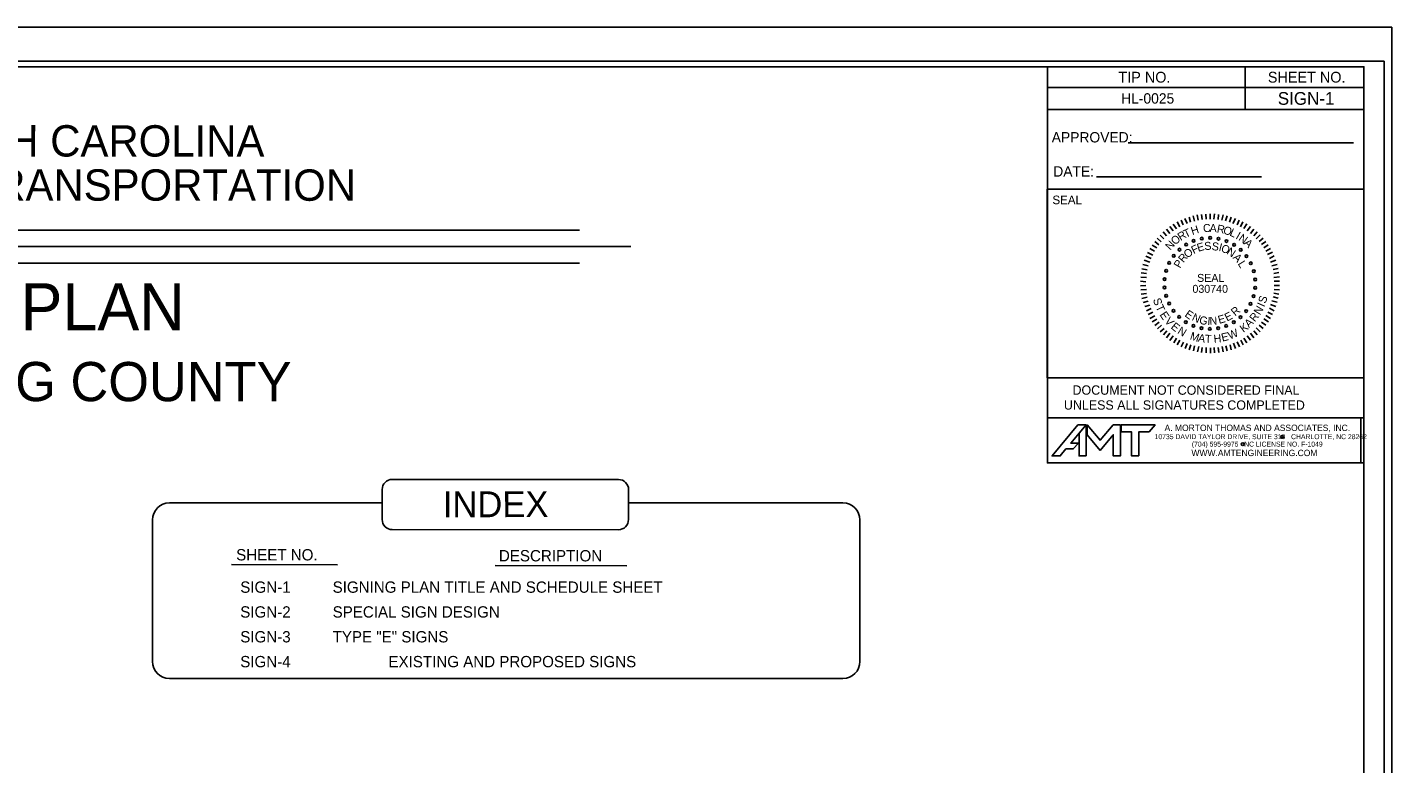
# Model space of a CAD drawing. Extents: x 2088591 to 2091186, y 751169 to 752405.
# Drawn here: x 2089946 to 2090752, y 751970 to 752405 of the extents above; entities that cross this region are included whole.
import ezdxf

# ---------------------------------------------------------------- set-up
doc = ezdxf.new("R2010")
doc.units = 0
for name, color, linetype in [('Default', 7, 'Continuous'), ('DEV PRELIMINARY STAMP CELL', 7, 'Continuous'), ('MARK LEFT TURN ARROW CELL', 7, 'Continuous'), ('Sheet Block Title CELL', 7, 'Continuous'), ('Sheet Data Field CELL', 7, 'Continuous'), ('Sheet Plan CELL', 7, 'Continuous'), ('Sheet Plot Border Inside CELL', 7, 'Continuous'), ('Sheet Plot Border Outside CELL', 7, 'Continuous'), ('Sheet Sticker Incomplete CELL', 7, 'Continuous'), ('Sheet Title CELL', 7, 'Continuous'), ('Typical Detail Wedge1 CELL', 7, 'Continuous')]:
    doc.layers.add(name, color=color, linetype=linetype)

msp = doc.modelspace()

# ---------------------------------------------------------------- linework, layer by layer
at = {"layer": 'Default'}
msp.add_line((2090595.95, 752336.5), (2090728.98, 752336.5), dxfattribs=at)
at = {"layer": 'DEV PRELIMINARY STAMP CELL'}
for p, q in [((2090627.21, 752291.02), (2090628.34, 752288.14)), ((2090629.34, 752292.02), (2090630.84, 752289.02)), ((2090631.96, 752292.77), (2090632.84, 752289.77)), ((2090634.34, 752293.52), (2090635.21, 752290.39)), ((2090636.71, 752294.02), (2090637.34, 752291.02)), ((2090639.34, 752294.39), (2090639.59, 752291.39)), ((2090641.71, 752294.52), (2090642.09, 752291.52)), ((2090644.34, 752294.77), (2090644.34, 752291.52)), ((2090646.96, 752294.77), (2090646.59, 752291.52)), ((2090649.34, 752294.39), (2090649.09, 752291.39)), ((2090651.96, 752294.02), (2090651.34, 752291.02)), ((2090654.34, 752293.52), (2090653.46, 752290.52)), ((2090656.71, 752292.77), (2090655.84, 752289.77)), ((2090659.34, 752292.02), (2090657.84, 752289.02)), ((2090661.46, 752291.02), (2090660.34, 752288.14)), ((2090616.59, 752284.02), (2090618.59, 752281.64)), ((2090618.59, 752285.64), (2090620.59, 752283.02)), ((2090620.59, 752287.14), (2090622.46, 752284.64)), ((2090622.59, 752288.52), (2090624.46, 752285.77)), ((2090624.96, 752290.02), (2090626.46, 752287.02)), ((2090663.71, 752290.02), (2090662.21, 752287.02)), ((2090666.09, 752288.77), (2090664.21, 752286.02)), ((2090668.09, 752287.14), (2090666.21, 752284.64)), ((2090670.09, 752285.64), (2090668.09, 752283.14)), ((2090672.09, 752284.02), (2090670.09, 752281.77)), ((2090610.09, 752276.27), (2090612.84, 752274.64)), ((2090611.71, 752278.39), (2090614.09, 752276.39)), ((2090613.09, 752280.39), (2090615.46, 752278.27)), ((2090614.84, 752282.14), (2090617.09, 752280.02)), ((2090673.84, 752282.39), (2090671.59, 752280.02)), ((2090675.59, 752280.39), (2090673.21, 752278.39)), ((2090677.21, 752278.39), (2090674.59, 752276.64)), ((2090678.59, 752276.39), (2090675.96, 752274.64)), ((2090605.46, 752267.27), (2090608.71, 752266.27)), ((2090606.46, 752269.64), (2090609.46, 752268.39)), ((2090607.46, 752271.89), (2090610.46, 752270.39)), ((2090608.71, 752274.27), (2090611.46, 752272.64)), ((2090679.96, 752274.27), (2090677.21, 752272.64)), ((2090681.21, 752272.02), (2090678.21, 752270.64)), ((2090682.21, 752269.89), (2090679.46, 752268.39)), ((2090683.21, 752267.27), (2090679.96, 752266.27)), ((2090603.71, 752259.89), (2090606.84, 752259.52)), ((2090604.09, 752262.27), (2090607.21, 752261.64)), ((2090604.71, 752264.89), (2090607.84, 752264.02)), ((2090683.96, 752264.89), (2090680.84, 752264.02)), ((2090684.59, 752262.52), (2090681.46, 752261.89)), ((2090684.96, 752260.14), (2090681.96, 752259.52)), ((2090603.34, 752254.89), (2090606.46, 752254.64)), ((2090603.34, 752252.27), (2090606.46, 752252.52)), ((2090603.46, 752257.27), (2090606.71, 752257.14)), ((2090685.21, 752257.52), (2090681.96, 752257.14)), ((2090685.34, 752254.89), (2090682.21, 752254.89)), ((2090685.34, 752252.52), (2090682.21, 752252.52)), ((2090603.46, 752249.77), (2090606.71, 752250.14)), ((2090603.71, 752247.27), (2090606.84, 752247.77)), ((2090604.09, 752244.77), (2090607.21, 752245.52)), ((2090604.84, 752242.39), (2090607.84, 752243.14)), ((2090683.96, 752242.52), (2090680.84, 752243.39)), ((2090684.59, 752244.89), (2090681.46, 752245.77)), ((2090684.96, 752247.27), (2090681.96, 752247.89)), ((2090685.21, 752249.89), (2090682.21, 752250.14)), ((2090605.71, 752240.02), (2090608.71, 752240.89)), ((2090606.71, 752237.52), (2090609.46, 752238.77)), ((2090607.71, 752235.39), (2090610.46, 752236.77)), ((2090608.84, 752233.02), (2090611.71, 752234.52)), ((2090679.96, 752233.02), (2090677.21, 752234.77)), ((2090681.21, 752235.39), (2090678.46, 752236.77)), ((2090682.21, 752237.52), (2090679.46, 752239.02)), ((2090683.21, 752240.02), (2090679.96, 752241.14)), ((2090610.09, 752231.02), (2090612.84, 752232.64)), ((2090611.71, 752228.77), (2090614.21, 752230.77)), ((2090613.21, 752226.77), (2090615.59, 752229.02)), ((2090614.84, 752225.02), (2090617.21, 752227.14)), ((2090673.84, 752225.02), (2090671.59, 752227.39)), ((2090675.59, 752227.02), (2090673.21, 752229.02)), ((2090677.21, 752229.02), (2090674.59, 752230.77)), ((2090678.84, 752231.02), (2090675.96, 752232.77)), ((2090616.84, 752223.27), (2090618.84, 752225.64)), ((2090618.59, 752221.64), (2090620.59, 752224.27)), ((2090620.59, 752220.02), (2090622.46, 752222.64)), ((2090622.84, 752218.64), (2090624.46, 752221.39)), ((2090624.96, 752217.39), (2090626.46, 752220.27)), ((2090627.21, 752216.27), (2090628.59, 752219.02)), ((2090659.34, 752215.27), (2090658.09, 752218.39)), ((2090661.71, 752216.27), (2090660.34, 752219.27)), ((2090663.84, 752217.39), (2090662.46, 752220.27)), ((2090666.09, 752218.64), (2090664.21, 752221.39)), ((2090668.09, 752220.27), (2090666.21, 752222.77)), ((2090670.21, 752221.64), (2090668.09, 752224.27)), ((2090672.09, 752223.39), (2090670.09, 752225.64)), ((2090629.59, 752215.27), (2090630.84, 752218.27)), ((2090631.96, 752214.39), (2090632.96, 752217.39)), ((2090634.59, 752213.89), (2090635.21, 752216.89)), ((2090636.96, 752213.27), (2090637.59, 752216.39)), ((2090639.34, 752212.89), (2090639.71, 752215.89)), ((2090641.96, 752212.64), (2090642.09, 752215.89)), ((2090644.59, 752212.52), (2090644.59, 752215.64)), ((2090646.96, 752212.64), (2090646.71, 752215.89)), ((2090649.46, 752212.89), (2090649.09, 752215.89)), ((2090652.09, 752213.27), (2090651.46, 752216.39)), ((2090654.46, 752213.89), (2090653.71, 752216.89)), ((2090656.84, 752214.39), (2090656.09, 752217.39))]:
    msp.add_line(p, q, dxfattribs=at)
for centre in [(2090630.17, 752276.53), (2090634.62, 752278.73), (2090639.39, 752280.06), (2090644.33, 752280.5), (2090649.27, 752280.03), (2090654.03, 752278.65), (2090658.46, 752276.42), (2090622.85, 752269.91), (2090626.21, 752273.56), (2090662.4, 752273.42), (2090665.73, 752269.74), (2090618.42, 752261.09), (2090620.23, 752265.71), (2090668.32, 752265.52), (2090670.09, 752260.89), (2090617.47, 752251.27), (2090617.49, 752256.22), (2090670.96, 752251.06), (2090670.98, 752256.01), (2090618.36, 752246.39), (2090620.14, 752241.76), (2090670.03, 752246.19), (2090622.73, 752237.54), (2090626.05, 752233.86), (2090662.25, 752233.72), (2090665.6, 752237.37), (2090668.22, 752241.57), (2090630, 752230.86), (2090634.43, 752228.63), (2090639.19, 752227.26), (2090644.12, 752226.78), (2090649.06, 752227.22), (2090653.83, 752228.56), (2090658.28, 752230.75)]:
    msp.add_circle(centre, 0.788, dxfattribs=at)
at = {"layer": 'MARK LEFT TURN ARROW CELL'}
for p, q in [((2090665.02, 752356.38), (2090665.04, 752381.34)), ((2090577.26, 752316.61), (2090674.7, 752316.61))]:
    msp.add_line(p, q, dxfattribs=at)
at = {"layer": 'Sheet Block Title CELL'}
msp.add_lwpolyline([(2090751.52, 752404.71), (2089068.61, 752404.71), (2089068.61, 751308.81), (2090751.52, 751308.81)], close=True, dxfattribs=at)
at = {"layer": 'Sheet Plan CELL'}
for p, q in [((2090751.52, 752404.71), (2090751.52, 752404.71)), ((2090747.03, 752384.71), (2090747.03, 752384.71))]:
    msp.add_line(p, q, dxfattribs=at)
at = {"layer": 'Sheet Plot Border Outside CELL'}
msp.add_lwpolyline([(2090548.29, 752174.37), (2090733.32, 752174.37), (2090733.32, 752147.74), (2090548.29, 752147.74)], close=True, dxfattribs=at)
at = {"layer": 'Sheet Sticker Incomplete CELL'}
for points in [[(2090735.1, 752381.4), (2089235.1, 752381.4), (2089235.1, 751331.4), (2090735.1, 751331.4)], [(2090548.29, 752381.4), (2090735.1, 752381.4), (2090735.1, 752147.74), (2090548.29, 752147.74)], [(2090548.29, 752381.4), (2090735.1, 752381.4), (2090735.1, 752356.33), (2090548.29, 752356.33)], [(2090548.29, 752381.4), (2090665.04, 752381.4), (2090665.04, 752369.19), (2090548.29, 752369.19)], [(2090665.04, 752381.4), (2090735.1, 752381.4), (2090735.1, 752369.19), (2090665.04, 752369.19)], [(2090548.29, 752369.19), (2090665.02, 752369.19), (2090665.02, 752356.33), (2090548.29, 752356.33)], [(2090665.04, 752369.19), (2090735.1, 752369.19), (2090735.1, 752356.33), (2090665.04, 752356.33)], [(2090548.25, 752309.27), (2090735.1, 752309.27), (2090735.1, 752197.87), (2090548.25, 752197.87)], [(2090548.29, 752197.87), (2090735.1, 752197.87), (2090735.1, 752174.37), (2090548.29, 752174.37)], [(2090548.29, 752174.37), (2090733.32, 752174.37), (2090733.32, 752147.74), (2090548.29, 752147.74)]]:
    msp.add_lwpolyline(points, close=True, dxfattribs=at)
for points in [[(2090566.97, 752165.32), (2090571.17, 752170.24), (2090566.27, 752170.24), (2090551.08, 752151.94), (2090555.83, 752151.94), (2090559.24, 752156.06), (2090563.58, 752156.06), (2090566.57, 752159.51), (2090562.07, 752159.51), (2090566.97, 752165.32)], [(2090571.17, 752151.94), (2090571.17, 752170.24), (2090566.97, 752165.32), (2090566.97, 752151.94), (2090571.17, 752151.94)], [(2090579.4, 752155.17), (2090587.17, 752164.43), (2090587.17, 752151.94), (2090591.36, 752151.94), (2090591.36, 752170.24), (2090587.17, 752170.24), (2090579.4, 752161.11), (2090571.71, 752170.24), (2090571.71, 752164.41), (2090579.4, 752155.17)], [(2090602.22, 752151.94), (2090602.22, 752166.04), (2090608.3, 752166.04), (2090611.81, 752170.24), (2090591.9, 752170.24), (2090591.9, 752166.04), (2090598.03, 752166.04), (2090598.03, 752151.94), (2090602.22, 752151.94)]]:
    msp.add_lwpolyline(points, dxfattribs=at)
for centre in [(2090686.81, 752163.18), (2090663.55, 752158.82)]:
    msp.add_circle(centre, 0.833, dxfattribs=at)
at = {"layer": 'Sheet Title CELL'}
for p, q in [((2089579.98, 752285.08), (2090272.09, 752285.08)), ((2089548.01, 752275.34), (2090302.43, 752275.34)), ((2089579.98, 752265.58), (2090272.09, 752265.58)), ((2090155.64, 752114.41), (2090155.65, 752132.04)), ((2090301.06, 752114.34), (2090301.07, 752131.98)), ((2090066.74, 752087.77), (2090129.3, 752087.74)), ((2090222.31, 752087.2), (2090300.04, 752087.17))]:
    msp.add_line(p, q, dxfattribs=at)
for points in [[(2090161.66, 752138.04), (2090295.07, 752137.98)], [(2090030.06, 752124.15), (2090155.65, 752124.15)], [(2090301.07, 752124.15), (2090427.62, 752124.15)], [(2090020.06, 752030.62), (2090020.06, 752114.15)], [(2090437.62, 752114.15), (2090437.62, 752030.62)], [(2090161.64, 752108.41), (2090295.06, 752108.35)], [(2090427.62, 752020.62), (2090030.06, 752020.62)]]:
    msp.add_lwpolyline(points, dxfattribs=at)
for centre, radius, start, end in [((2090161.65, 752132.04), 6, 89.97341, 179.97341), ((2090295.07, 752131.98), 6, 359.97341, 89.97341), ((2090030.06, 752114.15), 10, 90, 180), ((2090427.62, 752114.15), 10, 0, 90), ((2090161.64, 752114.41), 6, 179.97341, 269.97341), ((2090295.06, 752114.35), 6, 269.97341, 359.97341), ((2090030.06, 752030.62), 10, 180, 270), ((2090427.62, 752030.62), 10, 270, 0)]:
    msp.add_arc(centre, radius, start, end, dxfattribs=at)
at = {"layer": 'Typical Detail Wedge1 CELL'}
msp.add_lwpolyline([(2090747.03, 752384.71), (2089081.6, 752384.71), (2089081.6, 751328.81), (2090747.03, 751328.81)], close=True, dxfattribs=at)

# ---------------------------------------------------------------- texts
at = {"layer": 'Default'}
for s, height, p in [('TIP NO.', 6.358, (2090590.22, 752372.11)), ('SHEET NO.', 6.358, (2090678.42, 752372.11)), ('HL-0025', 6.11, (2090591.81, 752359.71)), ('APPROVED:', 6.11, (2090550.85, 752336.79)), ('DATE:', 6.11, (2090551.76, 752316.65)), ('SIGN-1          SIGNING PLAN TITLE AND SCHEDULE SHEET', 6.6709, (2090071.88, 752071.19)), ('SIGN-2          SPECIAL SIGN DESIGN', 6.6709, (2090071.88, 752056.55)), ('SIGN-3          TYPE "E" SIGNS', 6.6709, (2090071.88, 752041.9)), ('SIGN-4   ', 6.671, (2090071.88, 752027.25)), ('   EXISTING AND PROPOSED SIGNS', 6.6709, (2090151.93, 752027.25))]:
    msp.add_text(s, height=height, dxfattribs=at).set_placement(p)
for s, height, rotation, p in [('SEAL', 5.094, 359.96412, (2090551.27, 752300.36)), ('INDEX', 15.257, 0.15565, (2090191.46, 752115.68)), ('SHEET NO.', 6.671, 359.97341, (2090069.46, 752090.28)), ('DESCRIPTION', 6.6709, 359.97341, (2090224.55, 752089.71))]:
    msp.add_text(s, height=height, rotation=rotation, dxfattribs=at).set_placement(p)
at = {"layer": 'DEV PRELIMINARY STAMP CELL'}
for s, height, rotation, p in [('R', 4.72, 32.17545, (2090626.96, 752278.64)), ('T', 4.72, 25.43578, (2090629.96, 752280.39)), ('H', 4.72, 17.74335, (2090633.84, 752282.14)), ('C', 4.72, 4.93991, (2090640.34, 752283.77)), ('A', 4.72, 357.97486, (2090643.96, 752284.02)), ('R', 4.72, 350.02156, (2090648.09, 752283.77)), ('O', 4.72, 343.0868, (2090651.71, 752283.14)), ('L', 4.72, 335.7459, (2090655.46, 752282.02)), ('I', 4.72, 330.80596, (2090659.09, 752280.27)), ('N', 4.72, 324.90384, (2090660.71, 752279.39)), ('N', 4.72, 48.06666, (2090620.84, 752272.89)), ('O', 4.72, 39.94421, (2090623.59, 752276.02)), ('F', 4.7, 26.39995, (2090634.59, 752270.89)), ('E', 4.7, 16.58893, (2090637.34, 752272.27)), ('S', 4.7, 4.46802, (2090641.09, 752273.27)), ('S', 4.7, 353.04145, (2090645.09, 752273.39)), ('I', 4.7, 345.48207, (2090649.09, 752272.89)), ('O', 4.7, 337.87488, (2090650.34, 752272.64)), ('N', 4.7, 327.39302, (2090653.71, 752271.27)), ('A', 4.72, 317.00507, (2090663.84, 752277.02)), ('P', 4.7, 60.12364, (2090626.59, 752262.27)), ('R', 4.7, 49.7478, (2090628.59, 752265.52)), ('O', 4.7, 38.25181, (2090630.96, 752268.27)), ('A', 4.7, 313.94377, (2090657.46, 752268.64)), ('L', 4.7, 301.53231, (2090660.46, 752265.27)), ('S', 4.72, 288.212, (2090610.52, 752244.17)), ('S', 4.72, 72.25788, (2090677.06, 752241.53)), ('T', 4.72, 295.62438, (2090612.01, 752239.77)), ('E', 4.72, 303.82249, (2090614.35, 752235.17)), ('E', 4.7, 324.86919, (2090628.96, 752234.52)), ('N', 4.7, 336.05836, (2090633.21, 752232.02)), ('E', 4.7, 15.80569, (2090649.71, 752229.77)), ('E', 4.7, 27.15681, (2090654.34, 752231.14)), ('R', 4.7, 40.34926, (2090659.09, 752234.14)), ('R', 4.72, 51.15031, (2090670.7, 752230.62)), ('N', 4.72, 59.37257, (2090673.77, 752234.67)), ('I', 4.72, 66.04639, (2090676.19, 752239.42)), ('V', 4.72, 311.92979, (2090617.17, 752231.19)), ('E', 4.72, 320.23124, (2090620.79, 752227.48)), ('N', 4.72, 328.32899, (2090624.7, 752224.44)), ('G', 4.7, 347.48124, (2090637.59, 752230.02)), ('I', 4.7, 355.62459, (2090642.59, 752229.14)), ('N', 4.7, 3.12779, (2090644.09, 752229.14)), ('W', 4.72, 22.00576, (2090655.9, 752220.49)), ('K', 4.72, 36.141, (2090663.96, 752224.44)), ('A', 4.72, 43.52169, (2090667.25, 752227.28)), ('M', 4.72, 342.33704, (2090632.09, 752220.69)), ('A', 4.72, 350.18217, (2090636.95, 752219.4)), ('T', 4.72, 357.38659, (2090641.21, 752218.7)), ('H', 4.72, 6.01122, (2090646.65, 752218.57)), ('E', 4.72, 14.16475, (2090651.57, 752219.29))]:
    msp.add_text(s, height=height, rotation=rotation, dxfattribs=at).set_placement(p)
for s, p in [('SEAL', (2090636.66, 752254.56)), ('030740', (2090633.91, 752248.11))]:
    msp.add_text(s, height=4.699, dxfattribs=at).set_placement(p)
at = {"layer": 'Sheet Data Field CELL'}
for s, height, p in [('STATE OF NORTH CAROLINA', 18.4936, (2089737.14, 752328.6)), ('DEPARTMENT OF TRANSPORTATION', 18.4936, (2089693.7, 752302.59)), ('SIGNING PLAN', 27.7403, (2089775.22, 752226.1)), ('MECKLENBURG COUNTY', 23.1165, (2089724.3, 752184.31))]:
    msp.add_text(s, height=height, rotation=359.97341, dxfattribs=at).set_placement(p)
at = {"layer": 'Sheet Plot Border Inside CELL'}
for s, p in [('DOCUMENT NOT CONSIDERED FINAL', (2090563.1, 752188.01)), ('UNLESS ALL SIGNATURES COMPLETED', (2090558.03, 752179.21))]:
    msp.add_text(s, height=5.4995, rotation=359.96919, dxfattribs=at).set_placement(p)
at = {"layer": 'Sheet Sticker Incomplete CELL'}
for s, height, p in [('A. MORTON THOMAS AND ASSOCIATES, INC.', 3.75, (2090617.46, 752166.58)), ('10735 DAVID TAYLOR DRIVE, SUITE 310   CHARLOTTE, NC 28262', 2.9167, (2090611.54, 752161.79)), ('WWW.AMTENGINEERING.COM', 3.75, (2090633.31, 752151.79)), ('(704) 595-9975   NC LICENSE NO. F-1049', 2.9167, (2090633.53, 752157.41))]:
    msp.add_text(s, height=height, rotation=359.99952, dxfattribs=at).set_placement(p)
at = {"layer": 'Sheet Title CELL'}
msp.add_text('SIGN-1', height=7.5, dxfattribs=at).set_placement((2090684.27, 752359.01))

doc.saveas('drawing.dxf')
